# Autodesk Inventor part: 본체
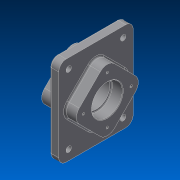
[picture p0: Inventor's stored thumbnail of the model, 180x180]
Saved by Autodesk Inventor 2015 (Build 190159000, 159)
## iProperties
Created: 2026-07
Part Number: 본체
Material: 일반
Document SubType Name: Modeling
Designer: user
Density: 1 g/cm^3
Appearance: 기본값
Author: user
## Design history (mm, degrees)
sketch "스케치2"
  geometry: L1 (-75, 90)-(75, 90); L2 (75, 90)-(75, -90); L3 (75, -90)-(-75, -90); L4 (-75, -90)-(-75, 90); L5 (-75, 90)-(75, -90); L6 (75, 90)-(-75, -90); 1 further point
  constraints: 12 end point, 2 midpoint, 2 parallel, 1 horizontal, 1 perpendicular
  dimensions: "d0" = 150 distance of L2.end L3.end; "d1" = 180 distance of L1.end L2.end
extrude "돌출1" new body sketch "스케치2" stored distance "d2" = 18; taper "d3" = 0 deg
sketch "스케치3"
  geometry: L1 (70.711, 0)-(0, -70.711); L2 (0, -70.711)-(-70.711, 0); L3 (-70.711, 0)-(0, 70.711); L4 (0, 70.711)-(70.711, 0); 2 further points
  constraints: 8 end point, 1 coincident, 9 other
  dimensions: "d4" = 100 distance of L2.end L3.end
extrude "돌출2" join sketch "스케치3" distance "d5" = 23; taper "d6" = 0 deg
sketch "스케치4"
  geometry: L1 (-70.711, 0)-(0, 70.711); L2 (0, 70.711)-(70.711, 0); L3 (70.711, 0)-(0, -70.711); L4 (0, -70.711)-(-70.711, 0); 2 further points
  constraints: 8 end point, 1 coincident, 9 other
  dimensions: "d7" = 100 distance of L3.end L1.start
extrude "돌출3" join sketch "스케치4" distance "d8" = 29; taper "d9" = 0 deg
sketch "스케치5"
  geometry: L1 (0, 70.711)-(70.711, 0) reference; L2 (70.711, 0)-(0, -70.711) reference; L3 (0, -70.711)-(-70.711, 0) reference; L4 (-70.711, 0)-(0, 70.711) reference; L5 (-90, 75)-(90, 75) reference; L6 (90, 75)-(90, -75) reference; L7 (90, -75)-(-90, -75) reference; L8 (-90, -75)-(-90, 75) reference; C1 r 11 at (70, -55); C2 r 11 at (-70, -55); C3 r 11 at (70, 55); C4 r 11 at (-70, 55); 1 further point
  constraints: 4 centre point, 2 horizontal alignment, 1 vertical alignment
  dimensions: "d10" = 11 radius of C1; "d11" = 11 radius of C2; "d12" = 140 distance of C2.centre C1.centre; "d13" = 11 radius of C3; "d14" = 11 radius of C4; "d15" = 140 distance of C4.centre C3.centre; "d16" = 110 distance of C1.centre C3.centre; "d17" = 55 vertical distance of point (0, 0) C3.centre; "d18" = 70 horizontal distance of C4.centre point (0, 0)
extrude "돌출4" join sketch "스케치5" distance "d19" = 5; taper "d20" = 0 deg
hole "구멍1" diameter "d23" = 11; stored, may be unused: countersink angle "d27" = 90 deg, drill point angle "d29" = 0 deg; dims "d21" = 10, "d22" = 10, "d24" = 6, "d25" = 4, "d26" = 2, "d28" = 8
sketch "스케치6"
  geometry: C1 r 31 at (0, 0); 1 further point
  constraints: 1 centre point, 1 coincident
  dimensions: "d36" = 31 radius of C1
extrude "돌출5" cut sketch "스케치6" distance "d37" = 22; taper "d38" = 0 deg
sketch "스케치7"
  geometry: C1 r 31 at (0, 0); 1 further point
  constraints: 1 centre point, 1 coincident
  dimensions: "d39" = 31 radius of C1
extrude "돌출6" cut sketch "스케치7" distance "d40" = 22; taper "d41" = 0 deg
hole "구멍2" diameter "d44" = 54; stored, may be unused: countersink angle "d48" = 90 deg, drill point angle "d50" = 0 deg; dims "d42" = 10, "d43" = 10, "d45" = 6, "d46" = 4, "d47" = 2, "d49" = 8
sketch "스케치8"
  geometry: L1 (0, 0)-(-48, 0)
  constraints: 2 end point, 1 horizontal
  dimensions: "d51" = 48 distance of L1.start L1.end
hole "구멍3" sketch "스케치8" at (-48, 0) diameter "d52" = 4.917; stored, may be unused: countersink angle "d56" = 90 deg, drill point angle "d58" = 118 deg; dims "d53" = 10, "d54" = 4, "d55" = 2, "d57" = 13
sketch "스케치9"
  geometry: L1 (0, 0)-(48, 0); C1 r 2.458 at (48, 0) reference
  constraints: 2 end point, 1 horizontal
  dimensions: "d62" = 48 distance of L1.start L1.end (derived)
hole "구멍4" sketch "스케치9" at (48, 0) diameter "d63" = 4.917; stored, may be unused: countersink angle "d67" = 90 deg, drill point angle "d69" = 118 deg; dims "d64" = 10, "d65" = 4, "d66" = 2, "d68" = 13
sketch "스케치10"
  geometry: L1 (90, -75)-(90, 75) reference; 2 further points
  constraints: 1 horizontal alignment, 1 other
  dimensions: "d73" = 15 distance from line of point (75, 0) L1
feature "엠보싱1" sketch "스케치10" dims "d0" = 150, "d1" = 180, "d7" = 100, "d74" = 0.5, "d75" = 0
chamfer "모따기1" distance "d76" = 1; stored, may be unused: second distance "d77" = 2, angle "d78" = 45 deg
fillet "모깎기1" dims "d79" = 15
fillet "모깎기2" dims "d80" = 3
fillet "모깎기3" dims "d81" = 20
fillet "모깎기4" dims "d82" = 20
fillet "모깎기5" dims "d83" = 3
fillet "모깎기6" dims "d84" = 3
fillet "모깎기7" dims "d85" = 3
fillet "모깎기8" dims "d86" = 1
node "솔리드1"
pattern_linear "직사각형 패턴1" dims "d32" = 110
pattern_circular "원형 패턴1" dims angle "d60" = 360 deg
pattern_circular "원형 패턴2" dims angle "d71" = 360 deg
node "절단 모서리 투영1"
